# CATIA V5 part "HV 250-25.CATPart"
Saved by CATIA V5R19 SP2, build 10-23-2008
Part number: HV 250-25
Bounding box of the stored display mesh (mm): x -18.951 to 18.951, y -18.952 to 18.952, z 0.053 to 119
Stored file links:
  C:\Users\Bora\Desktop\3D KATI MODEL- CATIA PART\HV serisi\HV 250\HV 250-25.CATPart
  C:\Program Files\Dassault Systemes\B19\intel_a\reffiles\standard\MetricThickPitch.txt
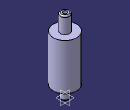
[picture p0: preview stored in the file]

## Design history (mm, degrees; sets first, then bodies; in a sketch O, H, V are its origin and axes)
Body1 (main body)
  Sketch1 on yz-plane, origin (0, 0, 0), H (0, 1, 0), V (0, 0, 1)
    point P1 (7.5, 117)
    point P3 (7.5, 117)
    point P7 (6, 17)
    point P8 (6, 1)
    point P10 (6, 1)
    point P12 (6, 17)
    line L1 (7.5, 117) -> (7.5, 93)
    arc A1 centre (5.5, 117) radius 2 from (7.5, 117) to (5.5, 119) ccw
    line L2 (6, 17) -> (6, 1)
    line L3 (5, 0) -> (6, 1)
    arc A2 centre (6, 18) radius 1 from (6, 19) to (6, 17) ccw
    line L4 (7.5, 93) -> (19, 93)
    line L5 (6, 19) -> (19, 19)
    line L6 (5, 0) -> (0, 0)
    line L7 (5.5, 119) -> (0, 119)
    point P13 (0, 119)
    line L8 (19, 93) -> (19, 19)
    horizontal: L4 H, L6 H
    tangency: L5 A2, L7 A1
    coincidence: P13 V, P1 P3, P7 P12, P8 P10
    vertical: L8 V
  Shaft1: profile Sketch1, axis Sketch1.V, angle 360
  Sketch2 on face of Shaft1 from Sketch1.L6, origin (0, 0, 0), H (1, 0, 0), V (0, -1, 0)
    point P1 (0, 0)
  Hole1: placed by Sketch2, at (0, 0, 0) direction (0, 0, 1), diameter 10.106, depth 19, threaded "M12", thread diameter 12, thread depth 19, pitch 1.75
  Sketch3 on face of Shaft1 from Sketch1.L7, origin (0, 0, 119), H (1, 0, 0), V (0, 1, 0)
    point P1 (0, 0)
  Hole2: placed by Sketch3, at (0, 0, 119) direction (0, 0, -1), diameter 6.647, depth 15, threaded "M8", thread diameter 8, thread depth 15, pitch 1.25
